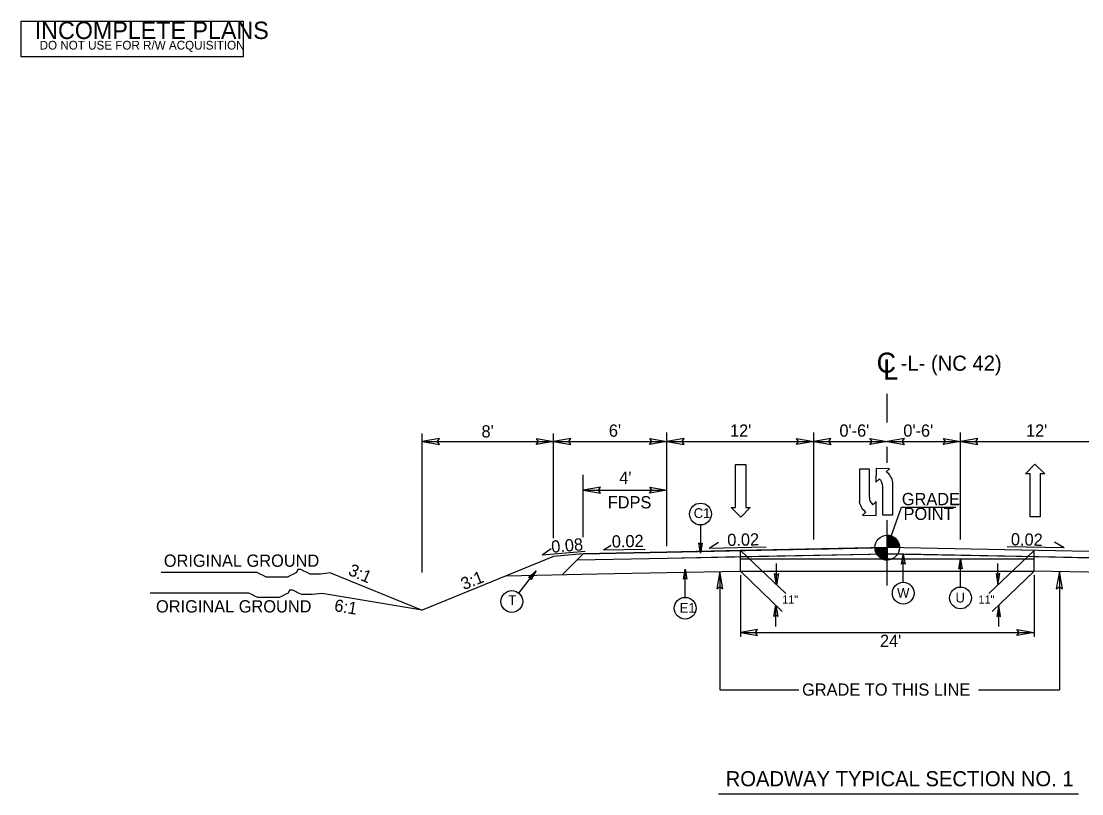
# Model space of a CAD drawing. Extents: x 2111095 to 2115970, y 670428 to 672393.
# Drawn here: x 2113319 to 2114021, y 671620 to 672132 of the extents above; entities that cross this region are included whole.
import ezdxf

# ---------------------------------------------------------------- set-up
doc = ezdxf.new("R2010")
doc.units = 0
for name, color, linetype in [('Old_Level_1', 7, 'Continuous'), ('Old_Level_11', 7, 'Continuous'), ('Old_Level_20', 7, 'Continuous'), ('Old_Level_3', 7, 'Continuous'), ('Prop Lane Arrow CELL', 7, 'Continuous'), ('Prop Leader Line Medium', 7, 'Continuous'), ('Prop Shade Medium', 7, 'Continuous'), ('Sheet Sticker Incomplete CELL', 7, 'Continuous'), ('Typical Grade Point Symbol CELL', 7, 'Continuous'), ('Typical Hinge Slope Arterial CELL', 7, 'Continuous'), ('Typical Pavement Slope CELL', 7, 'Continuous'), ('Typical Pavement Slope Information CELL', 7, 'Continuous'), ('Typical Shoulder Slope CELL', 7, 'Continuous'), ('Typical Shoulder Slope Information CELL', 7, 'Continuous'), ('Typical Terminator CELL', 7, 'Continuous'), ('Typical Text Centerline CELL', 7, 'Continuous'), ('Typical Text General CELL', 7, 'Continuous'), ('Typical Text Grade Point CELL', 7, 'Continuous')]:
    doc.layers.add(name, color=color, linetype=linetype)

msp = doc.modelspace()

# ---------------------------------------------------------------- linework, layer by layer
at = {"layer": 'Old_Level_1'}
for p, q in [((2113795.25, 671767.7), (2113795.25, 671781.28)), ((2113843.85, 671782.25), (2113892.45, 671783.22)), ((2114038.22, 671780.32), (2113892.45, 671783.22)), ((2113989.78, 671767.7), (2113989.78, 671781.28)), ((2113795.25, 671775.81), (2113892.45, 671775.81)), ((2113892.45, 671775.81), (2113989.62, 671775.81)), ((2113795.25, 671767.7), (2113892.45, 671767.7)), ((2113892.45, 671767.7), (2113989.62, 671767.7))]:
    msp.add_line(p, q, dxfattribs=at)
at = {"layer": 'Old_Level_11'}
for p, q in [((2113768.89, 671798.23), (2113768.89, 671779.57)), ((2113795.25, 671781.28), (2113825.32, 671752.8)), ((2113903.11, 671760.27), (2113903.11, 671778.96)), ((2113989.78, 671781.28), (2113959.71, 671752.8)), ((2113819.23, 671758.57), (2113819.23, 671772.62)), ((2113940.96, 671757.12), (2113940.96, 671775.81)), ((2113965.8, 671758.57), (2113965.8, 671772.62)), ((2113648.5, 671753.15), (2113659.98, 671767.91)), ((2113758.71, 671750.31), (2113758.71, 671769)), ((2113795.25, 671767.7), (2113823, 671740.99)), ((2113989.78, 671767.7), (2113962.03, 671740.98)), ((2113818.74, 671731.04), (2113818.74, 671745.09)), ((2113966.29, 671731.04), (2113966.29, 671745.09))]:
    msp.add_line(p, q, dxfattribs=at)
for points in [[(2113770.04, 671786.25), (2113768.89, 671779.57), (2113767.7, 671786.29), (2113768.89, 671785.44)], [(2113901.96, 671772.27), (2113903.11, 671778.96), (2113904.3, 671772.23), (2113903.11, 671773.09)], [(2113939.81, 671769.12), (2113940.96, 671775.81), (2113942.15, 671769.09), (2113940.96, 671769.94)], [(2113654.96, 671763.34), (2113659.98, 671767.91), (2113656.79, 671761.87), (2113656.37, 671763.27)], [(2113757.56, 671762.31), (2113758.71, 671769), (2113759.9, 671762.28), (2113758.71, 671763.13)], [(2113820.51, 671766), (2113819.23, 671758.57), (2113817.91, 671766.04), (2113819.23, 671765.09)], [(2113964.52, 671766), (2113965.8, 671758.57), (2113967.12, 671766.04), (2113965.8, 671765.09)], [(2113817.46, 671737.67), (2113818.74, 671745.09), (2113820.06, 671737.62), (2113818.74, 671738.57)], [(2113967.57, 671737.66), (2113966.29, 671745.09), (2113964.97, 671737.62), (2113966.29, 671738.57)]]:
    msp.add_lwpolyline(points, close=True, dxfattribs=at)
for centre in [(2113768.89, 671805.44), (2113903.11, 671753.05), (2113940.96, 671749.9), (2113643.94, 671747.55), (2113758.71, 671743.09)]:
    msp.add_circle(centre, 7.22, dxfattribs=at)
at = {"layer": 'Old_Level_3'}
for p, q in [((2113781.68, 671688.99), (2113833.91, 671688.99)), ((2113953.01, 671688.99), (2114006.45, 671688.99)), ((2113780.86, 671620.28), (2114019.18, 671620.28))]:
    msp.add_line(p, q, dxfattribs=at)
at = {"layer": 'Prop Lane Arrow CELL'}
for p, q in [((2113792.13, 671809.82), (2113792.13, 671838.17)), ((2113792.13, 671838.17), (2113798.81, 671838.17)), ((2113798.81, 671838.17), (2113798.81, 671809.82)), ((2113874.02, 671835.14), (2113874.02, 671813.78)), ((2113880.71, 671835.14), (2113874.02, 671835.14)), ((2113880.71, 671816.62), (2113880.71, 671835.14)), ((2113885.1, 671835.58), (2113885, 671826.46)), ((2113894.01, 671835.47), (2113885.1, 671835.58)), ((2113891.89, 671833.35), (2113894.01, 671835.47)), ((2113983.98, 671832.05), (2113990.25, 671838.43)), ((2113990.25, 671838.43), (2113996.73, 671832.05)), ((2113885, 671826.46), (2113887.13, 671828.59)), ((2113896.14, 671805), (2113896.14, 671826.36)), ((2113987.01, 671832.05), (2113983.98, 671832.05)), ((2113987.01, 671803.7), (2113987.01, 671832.05)), ((2113996.73, 671832.05), (2113993.7, 671832.05)), ((2113993.7, 671832.05), (2113993.7, 671803.7)), ((2113889.46, 671823.53), (2113889.46, 671805)), ((2113885.16, 671813.68), (2113883.03, 671811.55)), ((2113885.06, 671804.57), (2113885.16, 671813.68)), ((2113795.57, 671803.44), (2113789.09, 671809.82)), ((2113789.09, 671809.82), (2113792.13, 671809.82)), ((2113801.85, 671809.82), (2113795.57, 671803.44)), ((2113798.81, 671809.82), (2113801.85, 671809.82)), ((2113878.28, 671806.79), (2113876.15, 671804.67)), ((2113876.15, 671804.67), (2113885.06, 671804.57)), ((2113889.46, 671805), (2113896.14, 671805)), ((2113993.7, 671803.7), (2113987.01, 671803.7))]:
    msp.add_line(p, q, dxfattribs=at)
for centre, radius, start, end in [((2113885.66, 671824.76), 10.64, 8.67607, 53.98777), ((2113882.86, 671823.55), 6.63, 360, 49.65817), ((2113884.5, 671815.38), 10.64, 188.67607, 233.98777), ((2113887.3, 671816.59), 6.63, 180, 229.65817)]:
    msp.add_arc(centre, radius, start, end, dxfattribs=at)
at = {"layer": 'Prop Leader Line Medium'}
for p, q in [((2113892.45, 671865.97), (2113892.45, 671884.94)), ((2113584.65, 671766.85), (2113584.65, 671858.67)), ((2113671.62, 671789.41), (2113671.62, 671858.67)), ((2113746.65, 671784.23), (2113746.65, 671859.32)), ((2113843.85, 671788.68), (2113843.85, 671859.32)), ((2113941.05, 671788.68), (2113941.05, 671859.32)), ((2113584.65, 671853.48), (2113671.62, 671853.48)), ((2113671.62, 671853.48), (2113746.65, 671853.48)), ((2113746.65, 671853.48), (2113843.85, 671853.48)), ((2113843.85, 671853.48), (2113941.05, 671853.48)), ((2113892.45, 671839.26), (2113892.45, 671850)), ((2113941.05, 671853.48), (2114038.25, 671853.48)), ((2113691.26, 671790.14), (2113691.26, 671831.32)), ((2113691.26, 671821.28), (2113746.65, 671821.28)), ((2113892.45, 671758.19), (2113892.45, 671801.4)), ((2113781.68, 671767.43), (2113781.68, 671688.99)), ((2113795.25, 671764.9), (2113795.25, 671724.07)), ((2113989.78, 671764.9), (2113989.78, 671724.07)), ((2114006.45, 671767.37), (2114006.45, 671688.99)), ((2113795.25, 671727.08), (2113989.78, 671727.08))]:
    msp.add_line(p, q, dxfattribs=at)
at = {"layer": 'Prop Shade Medium'}
for p, q in [((2113691.26, 671779.2), (2113687.13, 671775.07)), ((2113746.65, 671780.31), (2113691.26, 671779.2)), ((2113795.25, 671781.28), (2113746.65, 671780.31)), ((2113746.73, 671776.26), (2113795.25, 671777.23)), ((2113892.45, 671783.22), (2113795.25, 671781.28)), ((2113795.25, 671777.23), (2113892.45, 671779.17)), ((2114038.22, 671780.32), (2113892.45, 671783.22)), ((2113892.45, 671783.22), (2113892.45, 671779.17)), ((2113892.45, 671779.17), (2113892.45, 671783.22)), ((2113892.45, 671779.17), (2113892.45, 671779.17)), ((2113687.13, 671775.07), (2113746.73, 671776.26))]:
    msp.add_line(p, q, dxfattribs=at)
msp.add_lwpolyline([(2113892.45, 671779.17), (2113989.78, 671777.23), (2114038.14, 671776.27)], dxfattribs=at)
at = {"layer": 'Sheet Sticker Incomplete CELL'}
msp.add_lwpolyline([(2113319.16, 672108.13), (2113319.16, 672131.63), (2113466.16, 672131.63), (2113466.16, 672108.13)], close=True, dxfattribs=at)
at = {"layer": 'Typical Grade Point Symbol CELL'}
for p, q in [((2113892.45, 671783.22), (2113892.45, 671791.38)), ((2113884.29, 671783.22), (2113892.45, 671783.22)), ((2113892.43, 671775.06), (2113892.45, 671783.22)), ((2113892.45, 671783.22), (2113892.43, 671775.06)), ((2113900.61, 671783.22), (2113892.45, 671783.22))]:
    msp.add_line(p, q, dxfattribs=at)
for points in [[(2113892.52, 671791.38), (2113892.52, 671791.38), (2113892.52, 671783.22)], [(2113892.69, 671791.38), (2113892.69, 671783.22)], [(2113892.85, 671791.36), (2113892.85, 671783.22)], [(2113893.01, 671791.36), (2113893.01, 671783.22)], [(2113893.18, 671791.34), (2113893.18, 671783.22)], [(2113893.34, 671791.32), (2113893.34, 671783.22)], [(2113893.5, 671791.3), (2113893.5, 671783.22)], [(2113893.67, 671791.29), (2113893.67, 671783.22)], [(2113893.83, 671791.27), (2113893.83, 671783.22)], [(2113893.99, 671791.23), (2113893.99, 671783.22)], [(2113894.16, 671791.19), (2113894.16, 671783.22)], [(2113894.32, 671791.16), (2113894.32, 671783.22)], [(2113894.48, 671791.12), (2113894.48, 671783.22)], [(2113894.64, 671791.07), (2113894.64, 671783.22)], [(2113894.81, 671791.03), (2113894.81, 671783.22)], [(2113894.97, 671790.98), (2113894.97, 671783.22)], [(2113895.13, 671790.92), (2113895.13, 671783.22)], [(2113895.3, 671790.87), (2113895.3, 671783.22)], [(2113895.46, 671790.8), (2113895.46, 671783.22)], [(2113895.62, 671790.72), (2113895.62, 671783.22)], [(2113895.79, 671790.65), (2113895.79, 671783.22)], [(2113895.95, 671790.58), (2113895.95, 671783.22)], [(2113896.11, 671790.51), (2113896.11, 671783.22)], [(2113896.28, 671790.42), (2113896.28, 671783.22)], [(2113896.44, 671790.33), (2113896.44, 671783.22)], [(2113896.6, 671790.23), (2113896.6, 671783.22)], [(2113896.77, 671790.14), (2113896.77, 671783.22)], [(2113896.93, 671790.03), (2113896.93, 671783.22)], [(2113897.09, 671789.93), (2113897.09, 671783.22)], [(2113897.26, 671789.8), (2113897.26, 671783.22)], [(2113897.42, 671789.69), (2113897.42, 671783.22)], [(2113897.58, 671789.56), (2113897.58, 671783.22)], [(2113897.75, 671789.42), (2113897.75, 671783.22)], [(2113897.91, 671789.27), (2113897.91, 671783.22)], [(2113898.07, 671789.13), (2113898.07, 671783.22)], [(2113898.23, 671788.97), (2113898.23, 671783.22)], [(2113898.4, 671788.8), (2113898.4, 671783.22)], [(2113898.56, 671788.62), (2113898.56, 671783.22)], [(2113898.72, 671788.42), (2113898.72, 671783.22)], [(2113898.89, 671788.22), (2113898.89, 671783.22)], [(2113899.05, 671788), (2113899.05, 671783.22)], [(2113899.21, 671787.77), (2113899.21, 671783.22)], [(2113899.38, 671787.51), (2113899.38, 671783.22)], [(2113899.54, 671787.24), (2113899.54, 671783.22)], [(2113899.7, 671786.95), (2113899.7, 671783.22)], [(2113899.87, 671786.61), (2113899.87, 671783.22)], [(2113900.03, 671786.23), (2113900.03, 671783.22)], [(2113900.19, 671785.77), (2113900.19, 671783.22)], [(2113900.36, 671785.21), (2113900.36, 671783.22)], [(2113900.52, 671784.38), (2113900.52, 671783.22)], [(2113884.33, 671783.22), (2113884.33, 671782.33)], [(2113884.49, 671783.22), (2113884.49, 671781.37)], [(2113884.66, 671783.22), (2113884.66, 671780.79)], [(2113884.82, 671783.22), (2113884.82, 671780.3)], [(2113884.98, 671783.22), (2113884.98, 671779.92)], [(2113885.15, 671783.22), (2113885.15, 671779.58)], [(2113885.31, 671783.22), (2113885.31, 671779.27)], [(2113885.47, 671783.22), (2113885.47, 671778.98)], [(2113885.64, 671783.22), (2113885.64, 671778.72)], [(2113885.8, 671783.22), (2113885.8, 671778.49)], [(2113885.96, 671783.22), (2113885.96, 671778.27)], [(2113886.13, 671783.22), (2113886.13, 671778.07)], [(2113886.29, 671783.22), (2113886.29, 671777.87)], [(2113886.45, 671783.22), (2113886.45, 671777.69)], [(2113886.61, 671783.22), (2113886.61, 671777.51)], [(2113886.78, 671783.22), (2113886.78, 671777.35)], [(2113886.94, 671783.22), (2113886.94, 671777.2)], [(2113887.1, 671783.22), (2113887.1, 671777.06)], [(2113887.27, 671783.22), (2113887.27, 671776.91)], [(2113887.43, 671783.22), (2113887.43, 671776.78)], [(2113887.59, 671783.22), (2113887.59, 671776.66)], [(2113887.76, 671783.22), (2113887.76, 671776.55)], [(2113887.92, 671783.22), (2113887.92, 671776.44)], [(2113888.08, 671783.22), (2113888.08, 671776.33)], [(2113888.25, 671783.22), (2113888.25, 671776.22)], [(2113888.41, 671783.22), (2113888.41, 671776.13)], [(2113888.57, 671783.22), (2113888.57, 671776.04)], [(2113888.74, 671783.22), (2113888.74, 671775.95)], [(2113888.9, 671783.22), (2113888.9, 671775.88)], [(2113889.06, 671783.22), (2113889.06, 671775.8)], [(2113889.23, 671783.22), (2113889.23, 671775.73)], [(2113889.39, 671783.22), (2113889.39, 671775.66)], [(2113889.55, 671783.22), (2113889.55, 671775.59)], [(2113889.71, 671783.22), (2113889.71, 671775.53)], [(2113889.88, 671783.22), (2113889.88, 671775.48)], [(2113890.04, 671783.22), (2113890.04, 671775.42)], [(2113890.2, 671783.22), (2113890.2, 671775.39)], [(2113890.37, 671783.22), (2113890.37, 671775.33)], [(2113890.53, 671783.22), (2113890.53, 671775.3)], [(2113890.69, 671783.22), (2113890.69, 671775.26)], [(2113890.86, 671783.22), (2113890.86, 671775.22)], [(2113891.02, 671783.22), (2113891.02, 671775.19)], [(2113891.18, 671783.22), (2113891.18, 671775.17)], [(2113891.35, 671783.22), (2113891.35, 671775.13)], [(2113891.51, 671783.22), (2113891.51, 671775.12)], [(2113891.67, 671783.22), (2113891.67, 671775.1)], [(2113891.84, 671783.22), (2113891.84, 671775.08)], [(2113892, 671783.22), (2113892, 671775.08)], [(2113892.16, 671783.22), (2113892.16, 671775.06)], [(2113892.33, 671783.22), (2113892.33, 671775.06), (2113892.33, 671775.06)]]:
    msp.add_lwpolyline(points, dxfattribs=at)
msp.add_circle((2113892.44, 671783.22), 8.16, dxfattribs=at)
for start, end in [(359.99048, 89.99047), (179.99048, 269.99048)]:
    msp.add_arc((2113892.44, 671783.22), 8.16, start, end, dxfattribs=at)
at = {"layer": 'Typical Hinge Slope Arterial CELL'}
for p, q in [((2113671.62, 671777.25), (2113584.65, 671741.92)), ((2113524, 671766.56), (2113584.65, 671741.92)), ((2113584.65, 671741.92), (2113518.47, 671752.95))]:
    msp.add_line(p, q, dxfattribs=at)
for points in [[(2113524, 671766.56), (2113517.35, 671765.73), (2113515.35, 671765.73), (2113512.35, 671765.73), (2113510.36, 671765.73), (2113508.36, 671766.72), (2113506.37, 671767.73), (2113504.37, 671768.73), (2113502.38, 671768.73), (2113501.37, 671766.72), (2113499.38, 671765.73), (2113497.38, 671764.73), (2113495.39, 671763.74), (2113493.39, 671763.74), (2113491.4, 671763.74), (2113489.4, 671763.74), (2113487.4, 671763.74), (2113485.41, 671763.74), (2113483.41, 671763.74), (2113481.42, 671763.74), (2113479.42, 671764.73), (2113477.43, 671765.73), (2113475.43, 671766.72), (2113472.43, 671766.72), (2113470.44, 671766.72), (2113411.77, 671766.72)], [(2113518.47, 671752.95), (2113511.82, 671752.12), (2113509.82, 671752.12), (2113506.83, 671752.12), (2113504.83, 671752.12), (2113502.84, 671753.12), (2113500.84, 671754.12), (2113498.84, 671755.12), (2113496.85, 671755.12), (2113495.85, 671753.12), (2113493.85, 671752.12), (2113491.86, 671751.12), (2113489.86, 671750.13), (2113487.86, 671750.13), (2113485.87, 671750.13), (2113483.87, 671750.13), (2113481.88, 671750.13), (2113479.88, 671750.13), (2113477.89, 671750.13), (2113475.89, 671750.13), (2113473.9, 671751.12), (2113471.9, 671752.12), (2113469.9, 671753.12), (2113466.91, 671753.12), (2113464.91, 671753.12), (2113404.49, 671753.12)]]:
    msp.add_lwpolyline(points, dxfattribs=at)
at = {"layer": 'Typical Pavement Slope CELL'}
for p, q in [((2113691.26, 671779.2), (2113677.41, 671765.35)), ((2113691.26, 671779.2), (2113746.65, 671780.31)), ((2113746.65, 671780.31), (2113892.45, 671783.22)), ((2113746.73, 671776.26), (2113892.53, 671779.17)), ((2114038.14, 671776.27), (2113892.37, 671779.17)), ((2113687.13, 671775.07), (2113746.73, 671776.26)), ((2113640.51, 671764.61), (2113700.4, 671765.81)), ((2113700.4, 671765.81), (2113746.49, 671766.73)), ((2113746.49, 671766.73), (2113795.25, 671767.7)), ((2114084.5, 671765.81), (2113989.78, 671767.7))]:
    msp.add_line(p, q, dxfattribs=at)
at = {"layer": 'Typical Pavement Slope Information CELL'}
for p, q in [((2113704.68, 671781.74), (2113709.66, 671784.75)), ((2113774.54, 671782.91), (2113780.88, 671786.74)), ((2113774.54, 671782.91), (2113812.29, 671783.67)), ((2114009.66, 671783.08), (2113971.91, 671783.83)), ((2114009.66, 671783.08), (2114003.32, 671786.91)), ((2113663.99, 671778.44), (2113670.08, 671782.67)), ((2113663.99, 671778.44), (2113692.41, 671780.83)), ((2113704.68, 671781.74), (2113732.14, 671782.29))]:
    msp.add_line(p, q, dxfattribs=at)
at = {"layer": 'Typical Shoulder Slope CELL'}
msp.add_line((2113691.26, 671779.2), (2113671.62, 671777.25), dxfattribs=at)
at = {"layer": 'Typical Terminator CELL'}
for points in [[(2113596.04, 671855.44), (2113584.65, 671853.48), (2113596.1, 671851.45), (2113594.65, 671853.48)], [(2113660.23, 671855.44), (2113671.62, 671853.48), (2113660.17, 671851.45), (2113661.63, 671853.48)], [(2113683.01, 671855.44), (2113671.62, 671853.48), (2113683.07, 671851.45), (2113681.62, 671853.48)], [(2113735.26, 671855.44), (2113746.65, 671853.48), (2113735.2, 671851.45), (2113736.65, 671853.48)], [(2113758.04, 671855.44), (2113746.65, 671853.48), (2113758.1, 671851.45), (2113756.65, 671853.48)], [(2113832.46, 671855.44), (2113843.85, 671853.48), (2113832.4, 671851.45), (2113833.85, 671853.48)], [(2113855.24, 671855.44), (2113843.85, 671853.48), (2113855.3, 671851.45), (2113853.85, 671853.48)], [(2113881.06, 671855.44), (2113892.45, 671853.48), (2113881, 671851.45), (2113882.45, 671853.48)], [(2113903.84, 671855.44), (2113892.45, 671853.48), (2113903.9, 671851.45), (2113902.45, 671853.48)], [(2113929.66, 671855.44), (2113941.05, 671853.48), (2113929.6, 671851.45), (2113931.05, 671853.48)], [(2113952.44, 671855.44), (2113941.05, 671853.48), (2113952.5, 671851.45), (2113951.05, 671853.48)], [(2113702.65, 671823.24), (2113691.26, 671821.28), (2113702.72, 671819.25), (2113701.26, 671821.28)], [(2113735.26, 671823.24), (2113746.65, 671821.28), (2113735.2, 671819.25), (2113736.65, 671821.28)], [(2113783.64, 671756.04), (2113781.68, 671767.43), (2113779.65, 671755.98), (2113781.68, 671757.44)], [(2114008.41, 671755.98), (2114006.45, 671767.37), (2114004.42, 671755.92), (2114006.45, 671757.37)], [(2113806.64, 671729.04), (2113795.25, 671727.08), (2113806.7, 671725.05), (2113805.25, 671727.08)], [(2113978.39, 671729.04), (2113989.78, 671727.08), (2113978.33, 671725.05), (2113979.78, 671727.08)]]:
    msp.add_lwpolyline(points, close=True, dxfattribs=at)
at = {"layer": 'Typical Text Grade Point CELL'}
for p, q in [((2113892.45, 671783.22), (2113901.87, 671810.03)), ((2113901.87, 671810.03), (2113937.96, 671810.03))]:
    msp.add_line(p, q, dxfattribs=at)

# ---------------------------------------------------------------- texts
at = {"layer": 'Old_Level_11'}
for p in [(2113822.91, 671746.16), (2113952.87, 671746.16)]:
    msp.add_text('11"', height=5.4, dxfattribs=at).set_placement(p)
at = {"layer": 'Old_Level_20'}
for s, height, p in [('C1', 6.461, (2113764.38, 671802.83)), ('W', 6.46, (2113899.01, 671750.04)), ('T', 6.46, (2113641.67, 671745.24)), ('U', 6.46, (2113937.68, 671746.89)), ('E1', 6.461, (2113755.06, 671740.08))]:
    msp.add_text(s, height=height, dxfattribs=at).set_placement(p)
at = {"layer": 'Prop Leader Line Medium'}
for s, height, p in [('-L- (NC 42)', 10, (2113901.37, 671900.29)), ("8'", 8.1, (2113623.89, 671856.11)), ("6'", 8.1, (2113708.19, 671856.62)), ("12'", 8.1, (2113788.4, 671856.64)), ("0'-6'", 8.1, (2113860.83, 671856.64)), ("0'-6'", 8.1, (2113903.12, 671856.64)), ("12'", 8.1, (2113984.35, 671856.64)), ("4'", 8.1, (2113715.05, 671825.39)), ('FDPS', 8.1, (2113707.43, 671809.19)), ("24'", 8.1, (2113887.7, 671717.5))]:
    msp.add_text(s, height=height, rotation=360, dxfattribs=at).set_placement(p)
at = {"layer": 'Sheet Sticker Incomplete CELL'}
for s, height, p in [('INCOMPLETE PLANS', 11.52, (2113328.11, 672119.83)), ('DO NOT USE FOR R/W ACQUISITION', 5.76, (2113331.36, 672112.88))]:
    msp.add_text(s, height=height, dxfattribs=at).set_placement(p)
at = {"layer": 'Typical Hinge Slope Arterial CELL'}
for s, rotation, p in [('ORIGINAL GROUND', 360, (2113413.58, 671770.54)), ('3:1', 336.4435, (2113535.05, 671765.48)), ('3:1', 21.96113, (2113612.2, 671755)), ('ORIGINAL GROUND', 360, (2113408.4, 671740.28)), ('6:1', 350.53768, (2113525.99, 671741.24))]:
    msp.add_text(s, height=8.1, rotation=rotation, dxfattribs=at).set_placement(p)
at = {"layer": 'Typical Pavement Slope Information CELL'}
for rotation, p in [(1.14574, (2113710.22, 671783.22)), (1.14574, (2113786.66, 671784.26)), (358.85426, (2113974.27, 671784.75))]:
    msp.add_text('0.02', height=8.1, rotation=rotation, dxfattribs=at).set_placement(p)
at = {"layer": 'Typical Shoulder Slope Information CELL'}
msp.add_text('0.08', height=8.1, rotation=4.76147, dxfattribs=at).set_placement((2113670.39, 671779.75))
at = {"layer": 'Typical Text Centerline CELL'}
for s, rotation, p in [('C', 360, (2113885.45, 671899)), ('L', 359.9469, (2113889.86, 671894.46))]:
    msp.add_text(s, height=13.29, rotation=rotation, dxfattribs=at).set_placement(p)
at = {"layer": 'Typical Text General CELL'}
msp.add_text('GRADE TO THIS LINE', height=8.1, rotation=360, dxfattribs=at).set_placement((2113836.1, 671685.22))
at = {"layer": 'Typical Text Grade Point CELL'}
for s, height, p in [('GRADE', 8.1, (2113902.14, 671811.3)), ('POINT', 8.1, (2113903.29, 671801.54)), ('ROADWAY TYPICAL SECTION NO. 1', 10, (2113785.53, 671625.26))]:
    msp.add_text(s, height=height, rotation=360, dxfattribs=at).set_placement(p)

doc.saveas('drawing.dxf')
